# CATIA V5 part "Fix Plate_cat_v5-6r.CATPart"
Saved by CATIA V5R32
Part number: Fix Plate
Bounding box of the stored display mesh (mm): x -45 to 45, y -150 to 150, z -40 to 230
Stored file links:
  D:\PROJECTS\Project 2022\CATIA V5 6R 2022\Resources\Tutorial Files\c16_catia_v5_6r2022_tut\Slide Curve\Fix Plate_cat_v5-6r.CATPart
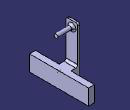
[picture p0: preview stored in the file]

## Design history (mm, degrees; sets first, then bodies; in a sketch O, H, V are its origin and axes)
Body1 (main body)
  Sketch1 on yz-plane, origin (0, 0, 0), H (0, 1, 0), V (0, 0, 1)
    line L1 (150, 40) -> (150, -40)
    line L2 (150, -40) -> (-150, -40)
    line L3 (-150, -40) -> (-150, 40)
    line L4 (-150, 40) -> (150, 40)
    length L4 = 300
    length L1 = 80
    vertical: L1 V, L3 V
    horizontal: L2 H, L4 H
    equidistance: L1 L3 O, L2 L4 O
  Pad1: profile Sketch1, direction (1, 0, 0), length 30
  Point1: type OnCurve, Support edge [face of Pad1 from Sketch1.L4 | end face of Pad1], Ratio 0.5
  Sketch2 on start face of Pad1, origin (0, 0, 0), H (0, -1, 0), V (0, 0, 1)
    circle A1 centre (0, 200) radius 10
    point P1 (0, 200)
    reference projected line E1 (-150, 40) -> (150, 40) from edge [start face of Pad1 | face of Pad1 from Sketch1.L4]
    radius A1 = 10
    distance E1 P1 = 160
    coincidence: P1 V
  Pad2: profile Sketch2, direction (1, 0, 0), length 45, mirrored extent
  Sketch3 on start face of Pad2, origin (-45, 0, 0), H (0, -1, 0), V (0, 0, 1)
    line L1 (30, -40) -> (-30, -40)
    line L2 (-30, -40) -> (-30, 230)
    line L3 (-30, 230) -> (30, 230)
    line L4 (30, 230) -> (30, -40)
    reference projected line E1 (-150, 40) -> (150, 40) from edge [start face of Pad1 | face of Pad1 from Sketch1.L4]
    length L3 = 60
    distance V L2 = 30
    distance E1 L3 = 190
    horizontal: L1 H, L3 H
    vertical: L2 V, L4 V
  Pad3: profile Sketch3, direction (1, 0, 0), length 10
  Sketch4 on end face of Pad3, origin (-35, 0, 0), H (0, 1, 0), V (0, 0, 1)
    line L1 (-30, 40) -> (30, 40)
    line L2 (30, 40) -> (30, -40)
    line L3 (30, -40) -> (-30, -40)
    line L4 (-30, -40) -> (-30, 40)
    reference projected line E1 (150, 40) -> (-150, 40) from edge [face of Pad1 from Sketch1.L4 | end face of Pad1]
    reference projected line E2 (-30, -40) -> (-30, 230) from edge [end face of Pad3 | face of Pad3 from Sketch3.L4]
    reference projected line E3 (-150, -40) -> (150, -40) from edge [face of Pad1 from Sketch1.L2 | end face of Pad1]
    reference projected line E4 (30, 230) -> (30, -40) from edge [end face of Pad3 | face of Pad3 from Sketch3.L2]
    horizontal: L1 H, L3 H
    vertical: L2 V, L4 V
    coincidence: L1 E1, L4 E2, L3 E3, L2 E4
  Pad4: profile Sketch4, direction (1, 0, 0), up to the existing solid (limit type 2)
  Fillet1: radius 10, on edge [face of Pad3 from Sketch3.L3 | face of Pad3]; edge [face of Pad2 from Sketch2.A1 | end face of Pad3]; edge [face of Pad4 | face of Pad3 from Sketch3.L3]; edge [end face of Pad3 | face of Pad1]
